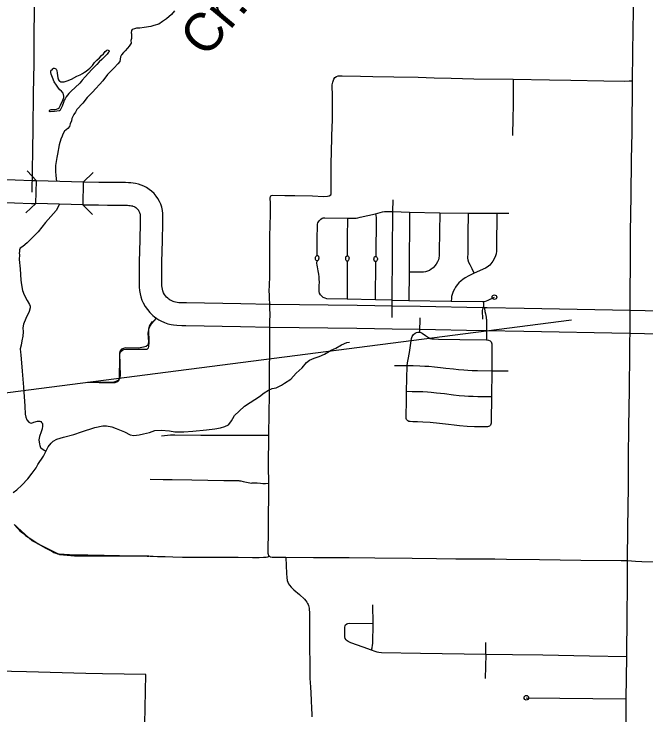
# Model space of a CAD drawing. Extents: x 670147 to 673275, y 705573 to 707613.
# Drawn here: x 671478.7 to 671618.2, y 706249.1 to 706403.8 of the extents above; entities that cross this region are included whole.
import ezdxf

# ---------------------------------------------------------------- set-up
doc = ezdxf.new("R2010")
doc.units = 0
for name, color, linetype in [('10', 7, 'Continuous'), ('32', 7, 'Continuous'), ('33', 7, 'Continuous'), ('34', 7, 'Continuous'), ('35', 7, 'Continuous'), ('37', 7, 'Continuous'), ('45', 7, 'Continuous'), ('6', 7, 'Continuous'), ('Default', 7, 'Continuous')]:
    doc.layers.add(name, color=color, linetype=linetype)

msp = doc.modelspace()

# ---------------------------------------------------------------- linework, layer by layer
at = {"layer": '10'}
for points in [[(671483.53, 706362), (671483.68, 706366.99), (671482.72, 706367.02), (671471.44, 706367.41)], [(671494.03, 706366.72), (671483.68, 706366.99)], [(671494.03, 706366.72), (671493.93, 706361.72), (671497.4, 706361.66), (671499.38, 706361.63), (671500.96, 706361.61), (671503.25, 706361.6), (671503.8, 706361.59), (671504.1, 706361.57), (671504.36, 706361.54), (671504.65, 706361.5), (671504.88, 706361.45), (671504.97, 706361.42), (671505.25, 706361.3), (671505.4, 706361.22), (671505.6, 706361.08), (671505.84, 706360.89), (671506.02, 706360.72), (671506.2, 706360.5), (671506.23, 706360.47), (671506.31, 706360.29), (671506.45, 706359.99), (671506.52, 706359.78), (671506.55, 706359.66), (671506.57, 706359.42), (671506.6, 706358.9), (671506.59, 706357.76), (671506.5, 706353.98), (671506.38, 706349.1), (671506.36, 706346.56), (671506.36, 706344.09), (671506.39, 706343.52), (671506.45, 706342.78), (671506.58, 706342.08), (671506.73, 706341.37), (671506.97, 706340.67), (671507.26, 706340.06), (671507.67, 706339.25), (671508.18, 706338.57), (671508.71, 706337.9), (671509.37, 706337.31), (671509.75, 706336.98), (671510.26, 706336.6), (671510.7, 706336.32), (671511.17, 706336.07), (671511.91, 706335.74), (671512.69, 706335.45), (671513.41, 706335.3), (671513.94, 706335.2), (671514.69, 706335.11), (671515.75, 706335.08), (671516.67, 706335.06), (671528.68, 706334.83), (671535.25, 706334.71), (671554.4, 706334.46), (671562.17, 706334.32), (671568.25, 706334.23), (671582.04, 706333.99), (671582.84, 706333.98), (671582.95, 706333.97), (671591.2, 706333.83), (671614.56, 706333.37), (671624.53, 706333.14)], [(671624.65, 706338.14), (671614.67, 706338.37), (671591.29, 706338.83), (671583.11, 706338.97), (671583.01, 706338.97), (671582.13, 706338.99), (671568.33, 706339.23), (671562.25, 706339.32), (671554.48, 706339.46), (671535.33, 706339.71), (671528.78, 706339.83), (671516.77, 706340.06), (671515.87, 706340.08), (671515.07, 706340.1), (671514.71, 706340.14), (671514.37, 706340.21), (671514.08, 706340.26), (671513.82, 706340.36), (671513.38, 706340.56), (671513.21, 706340.65), (671513.1, 706340.72), (671512.87, 706340.89), (671512.66, 706341.07), (671512.37, 706341.33), (671512.14, 706341.63), (671511.92, 706341.92), (671511.75, 706342.24), (671511.62, 706342.53), (671511.56, 706342.7), (671511.48, 706343.07), (671511.41, 706343.45), (671511.38, 706343.84), (671511.36, 706344.21), (671511.36, 706346.54), (671511.38, 706349.02), (671511.5, 706353.86), (671511.59, 706357.67), (671511.6, 706359.01), (671511.56, 706359.81), (671511.49, 706360.47), (671511.34, 706361.15), (671511.11, 706361.82), (671510.83, 706362.44), (671510.5, 706363.09), (671510.14, 706363.59), (671509.66, 706364.16), (671509.1, 706364.68), (671508.59, 706365.09), (671508, 706365.5), (671507.39, 706365.82), (671506.82, 706366.06), (671506.22, 706366.28), (671505.51, 706366.42), (671505.04, 706366.49), (671504.54, 706366.55), (671503.98, 706366.58), (671503.31, 706366.6), (671501.01, 706366.61), (671499.44, 706366.63), (671497.48, 706366.65), (671494.03, 706366.72)], [(671471.28, 706362.42), (671482.56, 706362.02), (671483.53, 706362)], [(671493.93, 706361.72), (671483.53, 706362)]]:
    msp.add_lwpolyline(points, dxfattribs=at)
at = {"layer": '32'}
msp.add_lwpolyline([(671478.94, 706291.01), (671479.3, 706290.59), (671479.67, 706290.16), (671480.04, 706289.77), (671480.58, 706289.29), (671481.29, 706288.72), (671482.65, 706287.82), (671484.08, 706286.92), (671485.61, 706286.03), (671487.08, 706285.24), (671487.52, 706285), (671487.95, 706284.83), (671488.32, 706284.71), (671488.69, 706284.66), (671489.84, 706284.57), (671490.96, 706284.52), (671492.68, 706284.47), (671494.06, 706284.44), (671494.99, 706284.43), (671495.98, 706284.39), (671497.03, 706284.38), (671497.74, 706284.38), (671498.64, 706284.39), (671501.99, 706284.29), (671505.05, 706284.22), (671508.15, 706284.16), (671508.47, 706284.15)], dxfattribs=at)
at = {"layer": '33'}
for points in [[(671483.41, 706417.75), (671483.37, 706414.35), (671483.14, 706400.12), (671483.1, 706392.91), (671482.97, 706386.25), (671482.9, 706378.45), (671482.64, 706364.52)], [(671615.46, 706415.56), (671615.45, 706415.25), (671615.37, 706413.32), (671615.39, 706412.2), (671615.39, 706411.5), (671615.34, 706408.91), (671615.32, 706407.76), (671615.33, 706404.37), (671615.25, 706400.38), (671615.18, 706395.26), (671615.11, 706389.08), (671615.04, 706377.64), (671614.95, 706371.67), (671614.86, 706363.66), (671614.72, 706355.66), (671614.68, 706349.8), (671614.63, 706341.34), (671614.61, 706335.87)], [(671557.92, 706389.98), (671562.57, 706389.94), (671567.88, 706389.84), (671571.42, 706389.71), (671575.19, 706389.65), (671580.22, 706389.51), (671588.86, 706389.44), (671596.93, 706389.28), (671601.57, 706389.19), (671608.91, 706389.06), (671613.53, 706389), (671614.47, 706389.05), (671615.11, 706389.08)], [(671562.21, 706336.82), (671562.19, 706340.68), (671562.26, 706351.38), (671562.34, 706360.23), (671562.39, 706362.78)], [(671545.61, 706350.51), (671545.64, 706354.52), (671545.67, 706356.84), (671545.7, 706357.45), (671545.8, 706357.76), (671546.06, 706358.15), (671546.45, 706358.55), (671546.76, 706358.75), (671546.98, 706358.82), (671547.33, 706358.86), (671552.39, 706358.73), (671553.75, 706358.73), (671554.27, 706358.75), (671554.57, 706358.8), (671555.14, 706358.97), (671558.49, 706359.73), (671560.03, 706360.12), (671560.5, 706360.2), (671560.95, 706360.24), (671562.34, 706360.23)], [(671558.49, 706359.73), (671558.56, 706359.35), (671558.62, 706358.92), (671558.57, 706350.32)], [(671562.34, 706360.23), (671566.01, 706360.08), (671572.66, 706359.96), (671579.02, 706359.89), (671585.24, 706359.82), (671587.92, 706359.83)], [(671566.01, 706360.08), (671565.93, 706346.84), (671565.83, 706340.62)], [(671572.66, 706359.96), (671572.56, 706351.41), (671572.53, 706350.5), (671572.45, 706349.96), (671572.37, 706349.59), (671572.18, 706349.11), (671571.9, 706348.63), (671571.62, 706348.22), (671571.24, 706347.8), (671570.8, 706347.47), (671570.38, 706347.21), (671569.95, 706347.04), (671569.54, 706346.93), (671569.11, 706346.87), (671568.64, 706346.82), (671565.93, 706346.84)], [(671585.24, 706359.82), (671585.19, 706352.4), (671585.18, 706351.46), (671585.09, 706350.9), (671584.97, 706350.42), (671584.7, 706349.8), (671584.39, 706349.25), (671583.98, 706348.68), (671583.7, 706348.39), (671583.45, 706348.18), (671583.13, 706347.96), (671582.74, 706347.71), (671580.26, 706346.61), (671579.13, 706346.02), (671578.29, 706345.58), (671577.74, 706345.22), (671577.4, 706344.92), (671576.92, 706344.46), (671576.52, 706344.01), (671576.19, 706343.53), (671575.9, 706343.05), (671575.66, 706342.58), (671575.42, 706341.88), (671575.28, 706341.44), (671575.24, 706341.06), (671575.21, 706340.46)], [(671580.26, 706346.61), (671579.82, 706347.54), (671579.36, 706348.43), (671579.09, 706348.97), (671578.97, 706349.45), (671578.89, 706349.98), (671578.93, 706351.04), (671578.97, 706355.22), (671579.02, 706359.89)], [(671552.32, 706350.42), (671552.34, 706354.46), (671552.39, 706358.73)], [(671545.61, 706350.51), (671545.73, 706350.49), (671545.84, 706350.43), (671545.91, 706350.35), (671545.96, 706350.22), (671546, 706350.04), (671545.99, 706349.9), (671545.96, 706349.7), (671545.91, 706349.55), (671545.8, 706349.43), (671545.72, 706349.37), (671545.61, 706349.34), (671545.52, 706349.35), (671545.42, 706349.41), (671545.35, 706349.48), (671545.29, 706349.63), (671545.26, 706349.89), (671545.27, 706350.14), (671545.32, 706350.3), (671545.39, 706350.4), (671545.45, 706350.46), (671545.53, 706350.48), (671545.66, 706350.5)], [(671552.32, 706350.42), (671552.39, 706350.41), (671552.5, 706350.36), (671552.57, 706350.27), (671552.62, 706350.14), (671552.66, 706349.96), (671552.65, 706349.82), (671552.62, 706349.63), (671552.57, 706349.47), (671552.46, 706349.35), (671552.38, 706349.29), (671552.27, 706349.26), (671552.18, 706349.27), (671552.09, 706349.33), (671552.01, 706349.4), (671551.95, 706349.56), (671551.92, 706349.81), (671551.93, 706350.06), (671551.98, 706350.22), (671552.05, 706350.32), (671552.11, 706350.38), (671552.19, 706350.4), (671552.32, 706350.42)], [(671558.57, 706350.32), (671558.65, 706350.31), (671558.75, 706350.25), (671558.83, 706350.17), (671558.88, 706350.03), (671558.92, 706349.86), (671558.91, 706349.71), (671558.88, 706349.52), (671558.82, 706349.36), (671558.72, 706349.24), (671558.63, 706349.18), (671558.53, 706349.16), (671558.43, 706349.17), (671558.34, 706349.22), (671558.27, 706349.29), (671558.2, 706349.45), (671558.17, 706349.7), (671558.19, 706349.95), (671558.23, 706350.11), (671558.31, 706350.22), (671558.36, 706350.27), (671558.44, 706350.3), (671558.57, 706350.32)], [(671562.19, 706340.68), (671558.49, 706340.76), (671552.24, 706340.88), (671547.75, 706340.97), (671547.4, 706341.07), (671546.93, 706341.28), (671546.64, 706341.55), (671546.35, 706341.86), (671546.16, 706342.23), (671546.06, 706342.58), (671546.06, 706343.04), (671546.09, 706343.83), (671546.12, 706344.71), (671546.1, 706345.24), (671546.06, 706345.79), (671545.97, 706346.39), (671545.85, 706347.12), (671545.7, 706347.98), (671545.62, 706348.39), (671545.59, 706348.81), (671545.61, 706349.34)], [(671552.27, 706349.26), (671552.24, 706340.88)], [(671558.53, 706349.16), (671558.4, 706340.77)], [(671562.19, 706340.68), (671565.83, 706340.62), (671575.21, 706340.46), (671582.27, 706340.34), (671582.63, 706340.38), (671583.39, 706340.69), (671584.74, 706341.31)], [(671582.27, 706340.34), (671582.31, 706339.76), (671582.33, 706339.22)], [(671582.33, 706339.22), (671582.18, 706338.96), (671582.08, 706338.69), (671582.05, 706338.39), (671582.06, 706337.68), (671582.08, 706337.12), (671582.08, 706336.49)], [(671582.33, 706339.22), (671582.44, 706339.01), (671582.55, 706338.8), (671582.65, 706338.19), (671582.77, 706337.63), (671582.84, 706337.24), (671582.9, 706336.91), (671582.92, 706336.48)], [(671614.06, 706283.16), (671612.72, 706283.16), (671603.81, 706283.22), (671594.7, 706283.38), (671587.37, 706283.44), (671584.8, 706283.47), (671580.75, 706283.5), (671576.24, 706283.49), (671571.93, 706283.55), (671566.58, 706283.66), (671558.39, 706283.75), (671552.68, 706283.8), (671544.81, 706283.83), (671538.69, 706283.86), (671535.69, 706283.89), (671535.36, 706283.93), (671535.08, 706284.15), (671535, 706284.27), (671534.87, 706284.52), (671534.84, 706284.72), (671534.9, 706290.26), (671534.96, 706300.19), (671534.88, 706304.09), (671534.99, 706310.81), (671535.01, 706315.77), (671535.12, 706319.62), (671535.14, 706324.25), (671535.2, 706330.32), (671535.18, 706335.11), (671535.21, 706336.26), (671535.29, 706337.21)], [(671568.29, 706336.73), (671568.2, 706333.57)], [(671583.03, 706336.47), (671582.96, 706331.9)], [(671614.61, 706335.87), (671614.53, 706329.13), (671614.47, 706320.89), (671614.35, 706312.7), (671614.26, 706305.93), (671614.22, 706299.44), (671614.1, 706290.42), (671614.06, 706283.16), (671614.03, 706277.49), (671613.97, 706271.15), (671613.85, 706261.98), (671613.77, 706252.69), (671613.68, 706239.92), (671613.68, 706230.44), (671613.67, 706230.15)], [(671565.5, 706326.15), (671565.59, 706326.86), (671565.72, 706327.6), (671566, 706329.09), (671566.18, 706330.13), (671566.38, 706331.69), (671566.48, 706332.22), (671566.62, 706332.61), (671566.89, 706333.07), (671567.24, 706333.34), (671567.54, 706333.5), (671567.82, 706333.58), (671568.2, 706333.57), (671568.47, 706333.51), (671568.83, 706333.36), (671569.54, 706332.87), (671570.23, 706332.39), (671570.56, 706332.23), (671570.92, 706332.14), (671571.27, 706332.11), (671572.38, 706332.08), (671577.12, 706332), (671582.96, 706331.9), (671583.45, 706331.84), (671583.83, 706331.65), (671584.01, 706331.46), (671584.11, 706331.26), (671584.18, 706331.02), (671584.19, 706330), (671584.17, 706325.01), (671584.09, 706319.41), (671584.06, 706313.88), (671584.02, 706313.53), (671583.98, 706313.27), (671583.84, 706313.06), (671583.64, 706312.88), (671583.46, 706312.78), (671583.24, 706312.72), (671582.97, 706312.71), (671581.74, 706312.7), (671580.35, 706312.74), (671578.7, 706312.81), (671577.03, 706312.93), (671575.85, 706313.07), (671574.59, 706313.21)], [(671587.81, 706324.98), (671584.17, 706325.01), (671581.04, 706325.04), (671579.83, 706325.09), (671578.91, 706325.13), (671578.02, 706325.2), (671576.81, 706325.3), (671575.72, 706325.41), (671574.03, 706325.6), (671572.82, 706325.74), (671571.49, 706325.88), (671570.28, 706326), (671569.36, 706326.05), (671568.29, 706326.11), (671566.78, 706326.16), (671566.28, 706326.16), (671565.5, 706326.15), (671562.68, 706326.2)], [(671574.59, 706313.21), (671572.65, 706313.46), (671570.56, 706313.66), (671568.93, 706313.76), (671567.75, 706313.82), (671566.72, 706313.83), (671566.12, 706313.85), (671565.88, 706313.9), (671565.66, 706314.02), (671565.52, 706314.15), (671565.37, 706314.35), (671565.27, 706314.53), (671565.26, 706314.74), (671565.27, 706315.81), (671565.31, 706317.74), (671565.35, 706320.55), (671565.5, 706326.15)], [(671565.35, 706320.55), (671566.6, 706320.53), (671568.24, 706320.5), (671568.96, 706320.47), (671569.95, 706320.41), (671570.79, 706320.37), (671571.95, 706320.23), (671573.73, 706320.03), (671575.71, 706319.79), (671576.98, 706319.64), (671578.17, 706319.55), (671579, 706319.5), (671580.03, 706319.47), (671581.11, 706319.42), (671582.77, 706319.4), (671584.09, 706319.41)], [(671640.97, 706282), (671640.55, 706282.11), (671640.1, 706282.25), (671639.63, 706282.34), (671639.16, 706282.41), (671638.26, 706282.46), (671635.62, 706282.57), (671632.86, 706282.67), (671629.65, 706282.75), (671628.19, 706282.79), (671623.43, 706282.86), (671617.26, 706282.92), (671615.87, 706282.99), (671614.98, 706283.07), (671614.06, 706283.16)], [(671557.59, 706263.45), (671557.73, 706263.97), (671557.83, 706264.54), (671557.88, 706264.92), (671557.95, 706269.33), (671557.93, 706273.39)], [(671613.85, 706261.98), (671605.73, 706262.11), (671595.41, 706262.3), (671588.76, 706262.38), (671582.82, 706262.46), (671568.45, 706262.72), (671559.8, 706262.86), (671559.22, 706262.89), (671558.84, 706262.97), (671558.44, 706263.14), (671557.59, 706263.45), (671555.77, 706264.09), (671553.07, 706265.07), (671552.5, 706265.3), (671552.27, 706265.46), (671552.03, 706265.7), (671551.84, 706265.99), (671551.75, 706266.36), (671551.73, 706267.12), (671551.72, 706267.82), (671551.73, 706268.51), (671551.79, 706268.79), (671551.91, 706269.03), (671552.16, 706269.21), (671552.42, 706269.29), (671552.7, 706269.36), (671557.95, 706269.33)], [(671582.82, 706262.46), (671582.84, 706265.09)], [(671582.82, 706262.46), (671582.72, 706257.2)], [(671591.78, 706252.92), (671599.21, 706252.86), (671613.77, 706252.69)]]:
    msp.add_lwpolyline(points, dxfattribs=at)
for centre in [(671584.74, 706341.31), (671591.78, 706252.92)]:
    msp.add_circle(centre, 0.5, dxfattribs=at)
at = {"layer": '34'}
for points in [[(671535.29, 706337.21), (671535.21, 706339.19), (671535.09, 706341.66), (671535.06, 706342.79), (671535.08, 706343.83), (671535.15, 706346.03), (671535.16, 706349.16), (671535.17, 706351.71), (671535.22, 706354.87), (671535.26, 706357.07), (671535.3, 706359.74), (671535.3, 706362.06), (671535.28, 706363.15), (671535.3, 706363.5), (671535.44, 706363.69), (671535.58, 706363.77), (671535.82, 706363.8), (671538.52, 706363.75), (671540.67, 706363.75), (671544.58, 706363.69), (671547.04, 706363.57), (671547.94, 706363.58), (671548.26, 706363.69), (671548.64, 706363.91), (671548.71, 706364.13), (671548.74, 706364.36), (671548.75, 706364.89), (671548.7, 706366.87), (671548.69, 706369.12), (671548.71, 706371.21), (671548.76, 706373.05), (671548.9, 706376.89), (671548.99, 706380.51), (671549.02, 706382.66), (671549.02, 706384.23), (671549.02, 706385.59), (671548.97, 706388.21), (671549.08, 706388.76), (671549.28, 706389.42), (671549.54, 706389.77), (671549.89, 706390.01), (671550.28, 706390.14), (671550.75, 706390.19), (671551.16, 706390.19), (671555.19, 706390.11), (671557.92, 706389.98)], [(671588.86, 706389.44), (671588.87, 706386.8), (671588.85, 706385.49), (671588.9, 706384.41), (671588.9, 706383.53), (671588.81, 706380.89), (671588.75, 706377.01)], [(671510.07, 706336.7), (671509.11, 706335.52), (671508.49, 706334.5), (671508.27, 706333.35), (671508.38, 706331.43), (671508.27, 706330.75), (671507.9, 706330.41), (671507.34, 706330.25), (671506.21, 706330.1), (671503.31, 706330.16), (671502.49, 706329.88), (671502.16, 706329.51), (671501.99, 706328.95), (671502.13, 706323.96), (671501.99, 706323.4), (671501.65, 706322.92), (671501.2, 706322.72), (671500.55, 706322.49), (671495.28, 706322.47)], [(671534.99, 706310.81), (671519.94, 706310.77), (671514.26, 706310.84), (671513.27, 706310.84), (671511.25, 706310.63)], [(671508.75, 706301.17), (671511.66, 706301.06), (671513.62, 706301.06), (671517.96, 706301), (671525.01, 706300.87), (671527.08, 706300.84), (671527.91, 706300.83), (671528.32, 706300.83), (671528.46, 706300.81), (671528.78, 706300.76), (671529.31, 706300.64), (671530.01, 706300.5), (671530.77, 706300.38), (671531.22, 706300.28)], [(671534.96, 706300.19), (671534.21, 706300.15), (671533.65, 706300.16), (671533.13, 706300.18), (671532.37, 706300.24), (671531.22, 706300.28)], [(671508.47, 706284.15), (671492.08, 706284.18), (671488.88, 706284.43), (671486.22, 706285.76), (671482.77, 706287.54), (671478.77, 706291.14)], [(671535.08, 706284.15), (671534.89, 706284.03), (671534.67, 706283.96), (671534.36, 706283.89), (671534.12, 706283.86), (671533.78, 706283.85), (671532.83, 706283.82), (671531.35, 706283.83), (671528.21, 706283.88), (671526.54, 706283.89), (671522.05, 706283.86), (671519.6, 706283.88), (671518.44, 706283.87), (671517.16, 706283.87), (671515.92, 706283.89), (671513.75, 706283.93), (671512.08, 706283.98), (671510.91, 706284.01), (671510.42, 706284.01), (671509.45, 706284.08), (671508.81, 706284.12), (671508.47, 706284.15)], [(671538.69, 706283.86), (671538.77, 706282.14), (671538.89, 706280.32), (671538.94, 706279.46), (671539.03, 706278.81), (671539.15, 706278.43), (671539.3, 706278.07), (671539.5, 706277.76), (671539.87, 706277.32), (671540.47, 706276.77), (671541.75, 706275.7), (671542.82, 706274.69), (671543.15, 706274.33), (671543.36, 706274.03), (671543.53, 706273.73), (671543.63, 706273.49), (671543.72, 706273.26), (671543.79, 706272.99), (671543.85, 706272.71), (671543.9, 706272.24), (671543.95, 706271.87), (671543.93, 706269.49), (671543.94, 706264.41), (671543.98, 706260.12), (671543.99, 706258.28), (671543.98, 706257.94), (671544, 706257.54), (671544.01, 706257.21), (671544.09, 706256.24), (671544.14, 706255.3), (671544.31, 706252.46), (671544.41, 706250.4), (671544.44, 706249.42), (671544.44, 706248.68)]]:
    msp.add_lwpolyline(points, dxfattribs=at)
at = {"layer": '35'}
for points in [[(671514.15, 706404.5), (671513.46, 706403.73), (671512.35, 706402.76), (671511.5, 706402.15), (671510.7, 706401.59), (671509.62, 706401.26), (671508.91, 706401.07), (671507.43, 706400.81), (671506.53, 706400.69), (671506.42, 706400.65)], [(671506.53, 706400.69), (671505.73, 706400.68), (671505.29, 706400.55), (671504.84, 706400.36), (671504.63, 706400.15), (671504.58, 706399.68), (671504.63, 706399.44), (671504.68, 706398.97), (671504.63, 706398.42), (671504.52, 706397.97), (671504.58, 706397.39), (671504.15, 706396.7), (671503.76, 706396.26), (671503.29, 706395.7), (671502.89, 706395.28), (671502.44, 706394.78), (671502.23, 706394.36), (671502.13, 706393.83), (671502.07, 706393.36), (671501.68, 706392.81), (671500.84, 706391.94), (671499.36, 706390.46), (671498.36, 706389.04), (671496.02, 706386.54), (671494.89, 706385.41), (671493.89, 706384.14), (671492.62, 706382.75), (671492.31, 706382.17), (671491.94, 706381.62), (671491.47, 706380.72), (671491.39, 706380.23), (671491.15, 706379.57), (671490.99, 706378.99), (671490.6, 706378.51), (671489.91, 706377.96), (671489.51, 706377.32), (671489.34, 706376.82), (671489.07, 706376.17), (671488.73, 706374.97), (671488.33, 706372.86), (671488.2, 706372.11), (671487.86, 706370.35), (671487.86, 706369.03), (671487.96, 706368.19), (671488.12, 706366.86)], [(671497.01, 706393.6), (671497.58, 706394.17), (671498.06, 706394.65), (671498.47, 706395.05), (671498.83, 706395.51), (671499.11, 706395.78), (671499.21, 706395.86), (671499.36, 706395.88), (671499.5, 706395.84), (671499.64, 706395.76), (671499.73, 706395.66), (671499.72, 706395.55), (671499.62, 706395.38), (671499.31, 706394.97), (671498.84, 706394.49), (671498.14, 706393.8), (671497.52, 706393.22), (671497.01, 706392.68)], [(671489.56, 706386.35), (671489.2, 706386.76), (671488.86, 706387.06), (671488.53, 706387.47), (671488.11, 706388.14), (671487.58, 706388.86), (671487.21, 706389.78), (671486.92, 706390.53), (671486.85, 706390.9), (671486.87, 706391.19), (671486.97, 706391.39), (671487.1, 706391.48), (671487.19, 706391.51), (671487.29, 706391.68), (671487.35, 706391.8), (671487.47, 706391.85), (671487.61, 706391.84), (671487.81, 706391.78), (671487.97, 706391.7), (671488.07, 706391.61), (671488.15, 706391.34), (671488.25, 706390.77), (671488.44, 706389.71), (671488.55, 706389.31), (671488.68, 706389.09), (671488.86, 706388.97), (671489.1, 706388.85), (671489.43, 706388.84), (671489.78, 706388.84), (671490.06, 706388.92), (671490.45, 706389.07), (671491.39, 706389.46), (671492.58, 706390.08), (671493.33, 706390.42), (671493.85, 706390.69), (671494.31, 706390.97), (671494.68, 706391.21), (671495.12, 706391.53), (671495.47, 706391.86), (671496.05, 706392.48), (671496.51, 706393.07), (671497.01, 706393.6)], [(671497.01, 706392.68), (671495.94, 706391.58), (671494.45, 706389.94), (671493.75, 706389.18), (671493.56, 706388.93), (671493.23, 706388.52), (671492.24, 706387.62), (671491.33, 706386.77), (671490.84, 706386.25), (671490.55, 706385.9), (671490.24, 706385.52), (671490.01, 706385.1), (671489.83, 706384.76), (671489.63, 706384.27), (671489.34, 706383.46), (671488.94, 706382.62), (671488.83, 706382.45), (671488.67, 706382.41), (671487.65, 706382.26), (671486.71, 706382.25), (671486.58, 706382.27), (671486.54, 706382.36), (671486.57, 706382.51), (671486.61, 706382.59), (671486.72, 706382.69), (671486.9, 706382.71), (671487.33, 706382.74), (671487.8, 706382.74), (671488.14, 706382.79), (671488.45, 706382.94), (671488.71, 706383.12), (671489, 706383.67), (671489.49, 706384.81), (671489.72, 706385.38), (671489.76, 706385.68), (671489.69, 706386.08), (671489.56, 706386.35)], [(671488.79, 706361.84), (671488.01, 706360.46), (671485.72, 706357.8), (671484.05, 706355.76), (671482.63, 706354.28), (671481.66, 706353.31), (671480.71, 706352.53), (671480.11, 706352.1), (671479.98, 706351.74), (671479.96, 706351.39), (671479.88, 706351), (671479.92, 706350.63), (671479.91, 706349.66), (671480.08, 706347.58), (671480.23, 706345.08), (671480.41, 706344.01), (671480.64, 706342.82), (671480.97, 706341.87), (671481.67, 706340.55), (671482.18, 706339.72), (671482.31, 706339.3), (671482.29, 706338.93), (671482.08, 706338.16), (671481.32, 706336.62), (671480.84, 706335.39), (671480.7, 706334.56), (671480.74, 706333.7), (671480.7, 706332.69), (671480.49, 706331.72), (671480.35, 706330.75), (671480.12, 706329.89), (671480.19, 706329.18), (671480.21, 706328.59)], [(671485.83, 706307.41), (671486.31, 706308.27), (671486.91, 706309.09), (671487.4, 706309.54), (671488.18, 706309.95), (671489.65, 706310.39), (671491.97, 706311.04), (671493.64, 706311.58), (671496.55, 706312.59), (671498.33, 706312.89), (671499.15, 706312.89), (671500.31, 706312.74), (671501.29, 706312.35), (671503.1, 706311.61), (671504.38, 706310.92), (671505.21, 706310.8), (671506.34, 706310.95), (671507.3, 706311.19), (671508.6, 706311.49), (671509.79, 706311.93), (671511.22, 706311.96), (671513.06, 706311.85), (671514.25, 706311.58), (671515.27, 706311.59), (671516.2, 706311.59), (671518.17, 706311.75), (671521.24, 706312.02), (671523.04, 706312.28), (671524.33, 706312.5), (671525.24, 706312.76), (671526.03, 706313.12), (671526.35, 706313.53), (671526.7, 706314.06), (671527.05, 706314.55), (671527.4, 706315.23), (671528.39, 706316.16), (671529.63, 706317.23), (671530.84, 706318.09), (671532.89, 706319.4), (671533.92, 706320.21), (671534.89, 706320.77), (671535.68, 706321.17), (671536.55, 706321.33), (671537.77, 706321.91), (671538.42, 706322.31), (671539.84, 706323.22), (671541.03, 706324.55), (671542.29, 706325.76), (671543.26, 706326.88), (671543.97, 706327.45), (671544.95, 706327.86), (671546.05, 706328.19), (671547.26, 706328.75), (671548.75, 706329.62), (671549.77, 706330.06), (671551.01, 706330.77), (671552.2, 706331.28), (671552.8, 706331.41)], [(671480.21, 706328.59), (671480.56, 706324.99), (671480.85, 706321.47), (671481.13, 706317.23), (671481.23, 706315.48), (671481.35, 706314.81), (671481.58, 706314.28), (671482.04, 706313.74), (671482.27, 706313.56), (671482.63, 706313.55), (671483.13, 706313.76), (671483.9, 706313.96), (671484.47, 706313.95), (671484.68, 706313.86), (671484.82, 706313.68), (671485, 706313.46), (671485.05, 706313.21), (671485.02, 706312.82), (671484.93, 706312.3), (671484.7, 706311.63), (671484.36, 706310.6), (671484.23, 706309.87), (671484.33, 706308.9), (671484.42, 706308.6), (671484.59, 706308.17), (671484.98, 706307.83), (671485.53, 706307.48), (671485.75, 706307.25)], [(671478.58, 706298.21), (671479.37, 706298.82), (671480.45, 706299.8), (671481.79, 706301.23), (671482.77, 706302.47), (671483.6, 706303.68), (671483.99, 706304.37), (671485.23, 706306.23), (671485.83, 706307.41)]]:
    msp.add_lwpolyline(points, dxfattribs=at)
at = {"layer": '37'}
for points in [[(671481.64, 706369.18), (671483.69, 706366.99)], [(671494.02, 706366.72), (671496.18, 706368.81)], [(671483.52, 706362), (671481.33, 706359.95)], [(671496.02, 706359.57), (671493.94, 706361.72)]]:
    msp.add_lwpolyline(points, dxfattribs=at)
at = {"layer": '45'}
msp.add_lwpolyline([(671494.94, 706322.53), (671497.54, 706322.49), (671499.63, 706322.52), (671500.53, 706322.51), (671501.06, 706322.52), (671501.41, 706322.6), (671501.64, 706322.73), (671501.82, 706322.88), (671501.95, 706323.08), (671502.04, 706323.38), (671502.04, 706323.75), (671502.09, 706327.72), (671502.1, 706328.59), (671502.13, 706329.07), (671502.2, 706329.21), (671502.3, 706329.33), (671502.68, 706329.63), (671502.96, 706329.75), (671503.33, 706329.82), (671503.96, 706329.84), (671505.79, 706329.81), (671507.66, 706329.81), (671507.95, 706329.83), (671508.15, 706329.88), (671508.3, 706329.98), (671508.44, 706330.14), (671508.49, 706330.43), (671508.53, 706331.41), (671508.46, 706334.12), (671508.46, 706334.31), (671508.54, 706334.6), (671508.66, 706334.93), (671508.89, 706335.29), (671509.31, 706335.94)], dxfattribs=at)
at = {"layer": '6'}
msp.add_lwpolyline([(671507.36, 706231.95), (671507.52, 706241.68), (671507.61, 706247.14), (671507.67, 706250.67), (671507.79, 706258.02), (671498.29, 706258.2), (671494.58, 706258.27), (671481.52, 706258.61), (671468.24, 706258.94), (671468.6, 706285.24), (671455.58, 706285.63), (671446.22, 706285.86)], dxfattribs=at)
at = {"layer": 'Default'}
msp.add_line((671069.5, 706267.64), (671601.78, 706336.35), dxfattribs=at)

# ---------------------------------------------------------------- texts
at = {"layer": '35'}
msp.add_text('Cr.', height=8.448, rotation=50.0266, dxfattribs=at).set_placement((671521.15, 706393.88))

doc.saveas('drawing.dxf')
